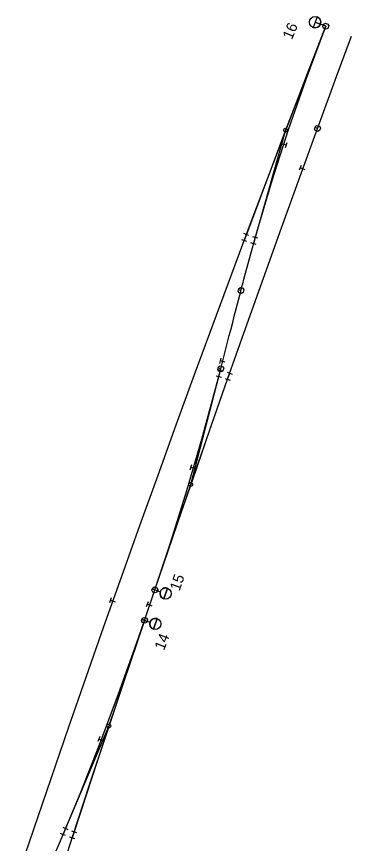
# Model space of a CAD drawing. Extents: x -733601 to -733291, y -1137892 to -1137187.
# Drawn here: x -733353.5 to -733290.9, y -1137341 to -1137186.7 of the extents above; entities that cross this region are included whole.
import ezdxf

# ---------------------------------------------------------------- set-up
doc = ezdxf.new("R2010")
doc.units = 0
doc.layers.add('SIT_PUV_ZELEZNICE', color=7, linetype='Continuous')

msp = doc.modelspace()

# ---------------------------------------------------------------- linework, layer by layer
at = {"layer": 'SIT_PUV_ZELEZNICE'}
for p, q in [((-733297.35, -1137186.77), (-733298.09, -1137188.74)), ((-733295.73, -1137188.52), (-733296.74, -1137188.13)), ((-733296.28, -1137188.57), (-733296.19, -1137188.34)), ((-733296.14, -1137188.89), (-733296.28, -1137188.57)), ((-733296.19, -1137188.34), (-733296.1, -1137188.1)), ((-733295.73, -1137188.52), (-733296.19, -1137188.34)), ((-733295.67, -1137189.07), (-733296.14, -1137188.89)), ((-733296.1, -1137188.1), (-733295.78, -1137187.96)), ((-733295.78, -1137187.96), (-733295.31, -1137188.14)), ((-733295.35, -1137188.93), (-733295.67, -1137189.07)), ((-733295.17, -1137188.46), (-733295.35, -1137188.93)), ((-733295.31, -1137188.14), (-733295.17, -1137188.46)), ((-733297.82, -1137207.64), (-733297.73, -1137207.4)), ((-733297.73, -1137207.4), (-733297.64, -1137207.17)), ((-733297.26, -1137207.57), (-733297.73, -1137207.4)), ((-733297.64, -1137207.17), (-733297.32, -1137207.02)), ((-733297.32, -1137207.02), (-733296.85, -1137207.19)), ((-733296.71, -1137207.51), (-733296.88, -1137207.98)), ((-733296.85, -1137207.19), (-733296.71, -1137207.51)), ((-733297.67, -1137207.96), (-733297.82, -1137207.64)), ((-733297.2, -1137208.13), (-733297.67, -1137207.96)), ((-733296.88, -1137207.98), (-733297.2, -1137208.13)), ((-733304.04, -1137210.4), (-733303.08, -1137210.69)), ((-733303.22, -1137211.17), (-733302.94, -1137210.21)), ((-733300.3, -1137214.47), (-733300.66, -1137215.4)), ((-733299.54, -1137215.29), (-733300.48, -1137214.93)), ((-733312.1, -1137237.93), (-733312.04, -1137237.68)), ((-733311.92, -1137238.23), (-733312.1, -1137237.93)), ((-733312.04, -1137237.68), (-733311.97, -1137237.44)), ((-733311.55, -1137237.81), (-733312.04, -1137237.68)), ((-733311.97, -1137237.44), (-733311.67, -1137237.26)), ((-733311.44, -1137238.36), (-733311.92, -1137238.23)), ((-733311.67, -1137237.26), (-733311.19, -1137237.39)), ((-733311.13, -1137238.18), (-733311.44, -1137238.36)), ((-733311.19, -1137237.39), (-733311.01, -1137237.69)), ((-733311.01, -1137237.69), (-733311.13, -1137238.18)), ((-733315.34, -1137250.46), (-733315.58, -1137251.43)), ((-733315.81, -1137252.33), (-733315.75, -1137252.09)), ((-733315.75, -1137252.09), (-733315.45, -1137251.91)), ((-733314.49, -1137251.19), (-733315.46, -1137250.95)), ((-733315.45, -1137251.91), (-733314.96, -1137252.04)), ((-733314.96, -1137252.04), (-733314.78, -1137252.34)), ((-733315.88, -1137252.58), (-733315.81, -1137252.33)), ((-733315.7, -1137252.88), (-733315.88, -1137252.58)), ((-733315.33, -1137252.46), (-733315.81, -1137252.33)), ((-733315.21, -1137253.01), (-733315.7, -1137252.88)), ((-733314.91, -1137252.83), (-733315.21, -1137253.01)), ((-733314.78, -1137252.34), (-733314.91, -1137252.83)), ((-733320.82, -1137270.38), (-733321.08, -1137271.34)), ((-733319.99, -1137271.13), (-733320.95, -1137270.86)), ((-733328.19, -1137293.77), (-733328.03, -1137293.3)), ((-733328.19, -1137293.77), (-733328.11, -1137293.53)), ((-733328.03, -1137294.09), (-733328.19, -1137293.77)), ((-733328.03, -1137294.09), (-733328.19, -1137293.77)), ((-733328.11, -1137293.53), (-733328.03, -1137293.3)), ((-733327.64, -1137293.69), (-733328.11, -1137293.53)), ((-733328.03, -1137293.3), (-733327.71, -1137293.14)), ((-733328.03, -1137293.3), (-733327.71, -1137293.14)), ((-733327.39, -1137293.78), (-733327.86, -1137293.62)), ((-733327.71, -1137293.14), (-733327.24, -1137293.3)), ((-733327.71, -1137293.14), (-733327.24, -1137293.3)), ((-733327.64, -1137293.69), (-733326.61, -1137294.04)), ((-733327.64, -1137293.69), (-733327.16, -1137293.85)), ((-733327.24, -1137293.3), (-733327.08, -1137293.62)), ((-733327.24, -1137293.3), (-733327.08, -1137293.62)), ((-733327.08, -1137293.62), (-733327.24, -1137294.09)), ((-733327.16, -1137293.85), (-733327.24, -1137294.09)), ((-733327.08, -1137293.62), (-733327.16, -1137293.85)), ((-733325.28, -1137293.38), (-733325.95, -1137295.37)), ((-733335.77, -1137295.18), (-733336.1, -1137296.12)), ((-733327.56, -1137294.25), (-733328.03, -1137294.09)), ((-733327.56, -1137294.25), (-733328.03, -1137294.09)), ((-733327.24, -1137294.09), (-733327.56, -1137294.25)), ((-733327.24, -1137294.09), (-733327.56, -1137294.25)), ((-733334.99, -1137295.98), (-733335.93, -1137295.65)), ((-733328.91, -1137295.9), (-733329.24, -1137296.84)), ((-733328.13, -1137296.7), (-733329.07, -1137296.37)), ((-733330.12, -1137299.45), (-733329.96, -1137298.98)), ((-733330.12, -1137299.45), (-733330.04, -1137299.22)), ((-733329.96, -1137299.77), (-733330.12, -1137299.45)), ((-733329.96, -1137299.77), (-733330.12, -1137299.45)), ((-733330.04, -1137299.22), (-733329.96, -1137298.98)), ((-733329.56, -1137299.38), (-733330.04, -1137299.22)), ((-733329.96, -1137298.98), (-733329.64, -1137298.82)), ((-733329.96, -1137298.98), (-733329.64, -1137298.82)), ((-733329.49, -1137299.93), (-733329.96, -1137299.77)), ((-733329.49, -1137299.93), (-733329.96, -1137299.77)), ((-733329.35, -1137299.45), (-733329.82, -1137299.29)), ((-733329.64, -1137298.82), (-733329.17, -1137298.98)), ((-733329.64, -1137298.82), (-733329.17, -1137298.98)), ((-733329.56, -1137299.38), (-733328.54, -1137299.72)), ((-733329.56, -1137299.38), (-733329.09, -1137299.54)), ((-733329.17, -1137299.77), (-733329.49, -1137299.93)), ((-733329.17, -1137299.77), (-733329.49, -1137299.93)), ((-733329.17, -1137298.98), (-733329.01, -1137299.3)), ((-733329.17, -1137298.98), (-733329.01, -1137299.3)), ((-733329.01, -1137299.3), (-733329.17, -1137299.77)), ((-733329.09, -1137299.54), (-733329.17, -1137299.77)), ((-733329.01, -1137299.3), (-733329.09, -1137299.54)), ((-733327.21, -1137299.06), (-733327.88, -1137301.05)), ((-733337.91, -1137321.06), (-733338.31, -1137321.98)), ((-733337.19, -1137321.92), (-733338.11, -1137321.52))]:
    msp.add_line(p, q, dxfattribs=at)
for points in [[(-733297.35, -1137186.77), (-733297.72, -1137187.75), (-733296.74, -1137188.13)], [(-733353.46, -1137347.78), (-733350.24, -1137338.32), (-733347, -1137328.86), (-733343.73, -1137319.41), (-733340.44, -1137309.96), (-733337.13, -1137300.53), (-733333.79, -1137291.1), (-733330.43, -1137281.68), (-733327.04, -1137272.27), (-733323.63, -1137262.87), (-733320.2, -1137253.48), (-733316.74, -1137244.1), (-733313.27, -1137234.72), (-733309.76, -1137225.35), (-733306.24, -1137216), (-733302.69, -1137206.65), (-733299.11, -1137197.31), (-733295.73, -1137188.52)], [(-733347.87, -1137346.51), (-733345.46, -1137340.96), (-733341.61, -1137331.74), (-733337.92, -1137322.44), (-733334.4, -1137313.08), (-733331.03, -1137303.67), (-733329.56, -1137299.38), (-733327.82, -1137294.22), (-733327.81, -1137294.2), (-733327.8, -1137294.18), (-733327.64, -1137293.69), (-733324.66, -1137284.71), (-733321.69, -1137275.16), (-733318.88, -1137265.56), (-733316.23, -1137255.92), (-733315.33, -1137252.46), (-733313.73, -1137246.24), (-733313.41, -1137245), (-733313.1, -1137243.82), (-733312.8, -1137242.64), (-733311.61, -1137238.04), (-733311.55, -1137237.81), (-733311.31, -1137236.86), (-733311.23, -1137236.56), (-733311, -1137235.68), (-733308.59, -1137226.91), (-733305.74, -1137217.32), (-733302.68, -1137207.81), (-733299.4, -1137198.36), (-733295.98, -1137189.17), (-733295.91, -1137188.99), (-733295.84, -1137188.81), (-733295.73, -1137188.52)], [(-733295.73, -1137188.52), (-733303.23, -1137207.91), (-733310.53, -1137227.39)], [(-733296.74, -1137188.13), (-733297.72, -1137187.75), (-733298.09, -1137188.74)], [(-733346.02, -1137349.11), (-733342.93, -1137339.6), (-733339.82, -1137330.09), (-733336.68, -1137320.6), (-733333.51, -1137311.11), (-733330.33, -1137301.64), (-733327.12, -1137292.16), (-733323.88, -1137282.7), (-733320.62, -1137273.25), (-733317.34, -1137263.8), (-733314.04, -1137254.36), (-733310.71, -1137244.93), (-733307.36, -1137235.51), (-733303.98, -1137226.1), (-733300.58, -1137216.69), (-733297.26, -1137207.57), (-733297.16, -1137207.3), (-733293.71, -1137197.91), (-733290.92, -1137190.37)], [(-733303.23, -1137207.91), (-733308.88, -1137227.93)], [(-733310.06, -1137227.56), (-733310.99, -1137227.21)], [(-733310.53, -1137227.39), (-733310.88, -1137228.32), (-733310.95, -1137228.51)], [(-733310.48, -1137228.69), (-733311.41, -1137228.34)], [(-733308.73, -1137229.22), (-733309.69, -1137228.95)], [(-733308.4, -1137228.06), (-733309.36, -1137227.79)], [(-733308.88, -1137227.93), (-733309.15, -1137228.89), (-733309.21, -1137229.08)], [(-733316.18, -1137253.75), (-733315.22, -1137254.01)], [(-733315.88, -1137252.59), (-733314.91, -1137252.85)], [(-733315.7, -1137253.88), (-733315.45, -1137252.91), (-733315.39, -1137252.72)], [(-733314.12, -1137253.09), (-733313.18, -1137253.42)], [(-733314.05, -1137254.38), (-733313.71, -1137253.44), (-733313.65, -1137253.25)], [(-733327.64, -1137293.69), (-733320.94, -1137274), (-733314.05, -1137254.38)], [(-733320.94, -1137274), (-733315.7, -1137253.88)], [(-733314.52, -1137254.22), (-733313.57, -1137254.55)], [(-733325.95, -1137295.37), (-733325.28, -1137293.38)], [(-733329.56, -1137299.38), (-733336.23, -1137319.08), (-733342.69, -1137338.85)], [(-733327.88, -1137301.05), (-733327.21, -1137299.06)], [(-733336.23, -1137319.08), (-733344.31, -1137338.24)], [(-733343.84, -1137338.44), (-733344.77, -1137338.05)], [(-733344.31, -1137338.24), (-733344.69, -1137339.16), (-733344.77, -1137339.35)], [(-733342.21, -1137339), (-733343.16, -1137338.69)], [(-733344.31, -1137339.54), (-733345.23, -1137339.15)], [(-733342.58, -1137340.14), (-733343.53, -1137339.83)], [(-733342.69, -1137338.85), (-733343, -1137339.8), (-733343.06, -1137339.99)]]:
    msp.add_lwpolyline(points, dxfattribs=at)
for centre, radius in [((-733297.72, -1137187.75), 1.05), ((-733303.23, -1137207.91), 0.35), ((-733320.94, -1137274), 0.35), ((-733325.62, -1137294.37), 1.05), ((-733327.54, -1137300.05), 1.05), ((-733336.23, -1137319.08), 0.35)]:
    msp.add_circle(centre, radius, dxfattribs=at)
for centre, start, end in [((-733297.72, -1137187.75), 0, 69.4722), ((-733297.72, -1137187.75), 249.4722, 339.0348), ((-733297.72, -1137187.75), 339.0348, 0), ((-733325.62, -1137294.37), 71.3148, 180), ((-733325.62, -1137294.37), 180, 251.2373), ((-733327.54, -1137300.05), 71.2761, 180), ((-733327.54, -1137300.05), 180, 251.2761)]:
    msp.add_arc(centre, 1.05, start, end, dxfattribs=at)

# ---------------------------------------------------------------- texts
for s, rotation, p in [('16', 66.8982, (-733302.05, -1137191.14)), ('15', 70.7615, (-733323.03, -1137294.01)), ('14', 68.4998, (-733325.94, -1137305.1))]:
    msp.add_text(s, height=2, rotation=rotation, dxfattribs=at).set_placement(p)

doc.saveas('drawing.dxf')
